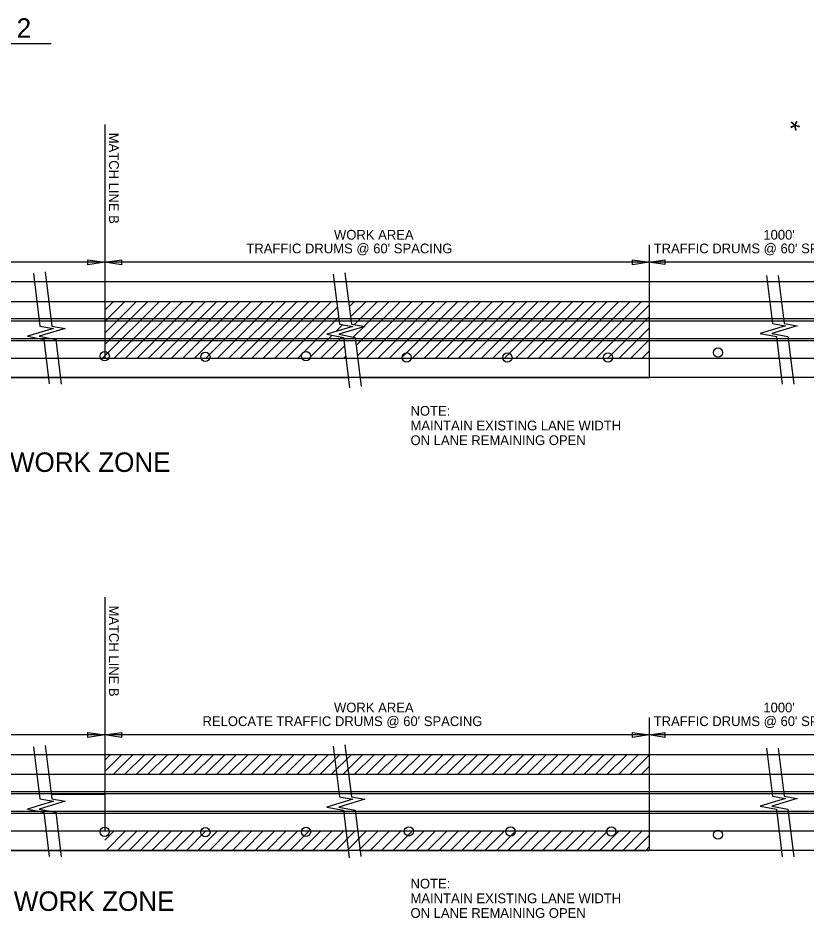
# Model space of a CAD drawing. Extents: x 1930579 to 1937984, y 596452 to 597630.
# Drawn here: x 1936944 to 1937430, y 596642 to 597197 of the extents above; entities that cross this region are included whole.
import ezdxf

# ---------------------------------------------------------------- set-up
doc = ezdxf.new("R2010")
doc.units = 0
doc.layers.add('Default', color=7, linetype='Continuous')
doc.layers.add('R_Border', color=7, linetype='Continuous')

msp = doc.modelspace()

# ---------------------------------------------------------------- linework, layer by layer
at = {"layer": 'Default'}
for p, q in [((1936835.84, 597181.22), (1936964.15, 597181.22)), ((1936997.05, 597131.34), (1936997.05, 596996.89)), ((1937332.4, 597057.24), (1937332.4, 596975.31)), ((1936997.05, 597046.45), (1936688.44, 597046.45)), ((1936986.74, 597044.9), (1936986.74, 597048)), ((1936986.74, 597048), (1936997.05, 597046.45)), ((1936997.05, 597046.45), (1936986.74, 597044.9)), ((1936997.05, 597046.45), (1937007.35, 597048)), ((1936997.05, 597047.93), (1936997.05, 596996.89)), ((1936997.05, 597047.92), (1936997.05, 596996.89)), ((1936997.05, 597047.92), (1936997.05, 596987.31)), ((1937332.4, 597046.45), (1936997.05, 597046.45)), ((1937007.35, 597044.9), (1936997.05, 597046.45)), ((1937007.35, 597048), (1937007.35, 597044.9)), ((1937322.09, 597044.9), (1937322.09, 597047.99)), ((1937322.09, 597047.99), (1937332.4, 597046.45)), ((1937332.4, 597046.45), (1937322.09, 597044.9)), ((1937332.4, 597046.45), (1937342.06, 597047.9)), ((1937342.06, 597045), (1937332.4, 597046.45)), ((1937498.74, 597046.45), (1937332.4, 597046.45)), ((1937342.06, 597047.9), (1937342.06, 597045)), ((1937498.74, 597034.31), (1936493.11, 597034.31)), ((1936493.11, 597022.31), (1937498.74, 597022.31)), ((1936995.74, 596987.31), (1937030.74, 597022.31)), ((1936997.05, 596995.68), (1937023.67, 597022.31)), ((1936997.05, 597002.75), (1937016.6, 597022.31)), ((1936997.05, 597009.83), (1937009.53, 597022.31)), ((1936997.05, 597016.9), (1937002.46, 597022.31)), ((1937002.81, 596987.31), (1937037.81, 597022.31)), ((1937009.89, 596987.31), (1937044.89, 597022.31)), ((1937016.96, 596987.31), (1937051.96, 597022.31)), ((1937024.03, 596987.31), (1937059.03, 597022.31)), ((1937031.1, 596987.31), (1937066.1, 597022.31)), ((1937038.17, 596987.31), (1937073.17, 597022.31)), ((1937045.24, 596987.31), (1937080.24, 597022.31)), ((1937052.31, 596987.31), (1937087.31, 597022.31)), ((1937059.38, 596987.31), (1937094.38, 597022.31)), ((1937066.45, 596987.31), (1937101.45, 597022.31)), ((1937073.53, 596987.31), (1937108.53, 597022.31)), ((1937080.6, 596987.31), (1937115.6, 597022.31)), ((1937087.67, 596987.31), (1937122.67, 597022.31)), ((1937094.74, 596987.31), (1937129.74, 597022.31)), ((1937101.81, 596987.31), (1937136.81, 597022.31)), ((1937147.64, 597018.99), (1937150.95, 597022.31)), ((1937148.42, 597012.71), (1937158.02, 597022.31)), ((1937150.83, 597008.04), (1937165.09, 597022.31)), ((1937152, 596995.07), (1937179.24, 597022.31)), ((1937152.76, 596988.76), (1937186.31, 597022.31)), ((1937156.84, 597006.98), (1937172.17, 597022.31)), ((1937158.38, 596987.31), (1937193.38, 597022.31)), ((1937165.45, 596987.31), (1937200.45, 597022.31)), ((1937172.52, 596987.31), (1937207.52, 597022.31)), ((1937179.59, 596987.31), (1937214.59, 597022.31)), ((1937186.66, 596987.31), (1937221.66, 597022.31)), ((1937193.73, 596987.31), (1937228.73, 597022.31)), ((1937200.8, 596987.31), (1937235.8, 597022.31)), ((1937207.88, 596987.31), (1937242.88, 597022.31)), ((1937214.95, 596987.31), (1937249.95, 597022.31)), ((1937222.02, 596987.31), (1937257.02, 597022.31)), ((1937229.09, 596987.31), (1937264.09, 597022.31)), ((1937236.16, 596987.31), (1937271.16, 597022.31)), ((1937243.23, 596987.31), (1937278.23, 597022.31)), ((1937250.3, 596987.31), (1937285.3, 597022.31)), ((1937257.37, 596987.31), (1937292.37, 597022.31)), ((1937264.44, 596987.31), (1937299.44, 597022.31)), ((1937271.52, 596987.31), (1937306.52, 597022.31)), ((1937278.59, 596987.31), (1937313.59, 597022.31)), ((1937285.66, 596987.31), (1937320.66, 597022.31)), ((1937292.73, 596987.31), (1937327.73, 597022.31)), ((1937108.88, 596987.31), (1937140.38, 597018.81)), ((1937299.8, 596987.31), (1937332.4, 597019.91)), ((1937498.74, 597011.52), (1936493.11, 597011.52)), ((1937498.74, 597010.14), (1936493.11, 597010.14)), ((1937115.95, 596987.31), (1937141.16, 597012.52)), ((1937306.87, 596987.31), (1937332.4, 597012.83)), ((1937139.45, 597003.73), (1937143.72, 597008.01)), ((1937150.22, 597000.37), (1937156.57, 597006.72)), ((1937313.94, 596987.31), (1937332.4, 597005.76)), ((1937498.74, 596999.34), (1936493.11, 596999.34)), ((1937123.02, 596987.31), (1937137.15, 597001.44)), ((1937130.09, 596987.31), (1937143.09, 597000.3)), ((1937321.01, 596987.31), (1937332.4, 596998.69)), ((1937498.74, 596998.03), (1936493.11, 596998.03)), ((1937137.17, 596987.31), (1937144.74, 596994.88)), ((1936493.11, 596987.31), (1937498.74, 596987.31)), ((1937144.24, 596987.31), (1937145.5, 596988.57)), ((1937328.08, 596987.31), (1937332.4, 596991.62)), ((1937498.74, 596975.31), (1936493.11, 596975.31)), ((1936757.75, 596975.31), (1937032.82, 596975.31)), ((1936970.07, 596975.31), (1936996.83, 596975.31)), ((1936996.83, 596975.31), (1937147.44, 596975.31)), ((1937155.09, 596975.31), (1937332.4, 596975.31)), ((1936997.05, 596839.97), (1936997.05, 596705.52)), ((1937332.4, 596765.87), (1937332.4, 596683.94)), ((1936997.05, 596755.08), (1936688.44, 596755.08)), ((1936986.74, 596753.53), (1936986.74, 596756.63)), ((1936986.74, 596756.63), (1936997.05, 596755.08)), ((1936997.05, 596755.08), (1936986.74, 596753.53)), ((1936997.05, 596755.08), (1937007.35, 596756.63)), ((1936997.05, 596756.56), (1936997.05, 596705.52)), ((1936997.05, 596756.55), (1936997.05, 596705.52)), ((1936997.05, 596756.55), (1936997.05, 596695.94)), ((1937332.4, 596755.08), (1936997.05, 596755.08)), ((1937007.35, 596753.53), (1936997.05, 596755.08)), ((1937007.35, 596756.63), (1937007.35, 596753.53)), ((1937322.09, 596753.53), (1937322.09, 596756.62)), ((1937322.09, 596756.62), (1937332.4, 596755.08)), ((1937332.4, 596755.08), (1937322.09, 596753.53)), ((1937332.4, 596755.08), (1937342.06, 596756.53)), ((1937498.74, 596755.08), (1937332.4, 596755.08)), ((1937342.06, 596753.63), (1937332.4, 596755.08)), ((1937342.06, 596756.53), (1937342.06, 596753.63)), ((1937498.74, 596742.94), (1936493.11, 596742.94)), ((1936997.05, 596732.6), (1937007.39, 596742.94)), ((1936997.05, 596739.67), (1937000.32, 596742.94)), ((1937002.46, 596730.94), (1937014.46, 596742.94)), ((1937009.53, 596730.94), (1937021.53, 596742.94)), ((1937016.6, 596730.94), (1937028.6, 596742.94)), ((1937023.67, 596730.94), (1937035.67, 596742.94)), ((1937030.74, 596730.94), (1937042.74, 596742.94)), ((1937037.81, 596730.94), (1937049.81, 596742.94)), ((1937044.89, 596730.94), (1937056.89, 596742.94)), ((1937051.96, 596730.94), (1937063.96, 596742.94)), ((1937059.03, 596730.94), (1937071.03, 596742.94)), ((1937066.1, 596730.94), (1937078.1, 596742.94)), ((1937073.17, 596730.94), (1937085.17, 596742.94)), ((1937080.24, 596730.94), (1937092.24, 596742.94)), ((1937087.31, 596730.94), (1937099.31, 596742.94)), ((1937094.38, 596730.94), (1937106.38, 596742.94)), ((1937101.45, 596730.94), (1937113.45, 596742.94)), ((1937108.53, 596730.94), (1937120.53, 596742.94)), ((1937115.6, 596730.94), (1937127.6, 596742.94)), ((1937122.67, 596730.94), (1937134.67, 596742.94)), ((1937129.74, 596730.94), (1937141.74, 596742.94)), ((1937136.81, 596730.94), (1937148.81, 596742.94)), ((1937143.88, 596730.94), (1937155.88, 596742.94)), ((1937150.95, 596730.94), (1937162.95, 596742.94)), ((1937158.02, 596730.94), (1937170.02, 596742.94)), ((1937165.09, 596730.94), (1937177.09, 596742.94)), ((1937172.17, 596730.94), (1937184.17, 596742.94)), ((1937179.24, 596730.94), (1937191.24, 596742.94)), ((1937186.31, 596730.94), (1937198.31, 596742.94)), ((1937193.38, 596730.94), (1937205.38, 596742.94)), ((1937200.45, 596730.94), (1937212.45, 596742.94)), ((1937207.52, 596730.94), (1937219.52, 596742.94)), ((1937214.59, 596730.94), (1937226.59, 596742.94)), ((1937221.66, 596730.94), (1937233.66, 596742.94)), ((1937228.73, 596730.94), (1937240.73, 596742.94)), ((1937235.8, 596730.94), (1937247.8, 596742.94)), ((1937242.88, 596730.94), (1937254.88, 596742.94)), ((1937249.95, 596730.94), (1937261.95, 596742.94)), ((1937257.02, 596730.94), (1937269.02, 596742.94)), ((1937264.09, 596730.94), (1937276.09, 596742.94)), ((1937271.16, 596730.94), (1937283.16, 596742.94)), ((1937278.23, 596730.94), (1937290.23, 596742.94)), ((1937285.3, 596730.94), (1937297.3, 596742.94)), ((1937292.37, 596730.94), (1937304.37, 596742.94)), ((1937299.44, 596730.94), (1937311.44, 596742.94)), ((1937306.52, 596730.94), (1937318.52, 596742.94)), ((1937313.59, 596730.94), (1937325.59, 596742.94)), ((1937320.66, 596730.94), (1937332.66, 596742.94)), ((1937327.73, 596730.94), (1937332.4, 596735.61)), ((1936493.11, 596730.94), (1937498.74, 596730.94)), ((1937498.74, 596720.15), (1936493.11, 596720.15)), ((1937498.74, 596718.77), (1936493.11, 596718.77)), ((1936964.36, 596718.71), (1936997.05, 596718.71)), ((1937498.74, 596707.98), (1936493.11, 596707.98)), ((1937498.74, 596706.66), (1936493.11, 596706.66)), ((1936493.11, 596695.94), (1937498.74, 596695.94)), ((1936997.05, 596690.17), (1937002.81, 596695.94)), ((1936997.89, 596683.94), (1937009.89, 596695.94)), ((1937004.96, 596683.94), (1937016.96, 596695.94)), ((1937012.03, 596683.94), (1937024.03, 596695.94)), ((1937019.1, 596683.94), (1937031.1, 596695.94)), ((1937026.17, 596683.94), (1937038.17, 596695.94)), ((1937033.24, 596683.94), (1937045.24, 596695.94)), ((1937040.31, 596683.94), (1937052.31, 596695.94)), ((1937047.38, 596683.94), (1937059.38, 596695.94)), ((1937054.45, 596683.94), (1937066.45, 596695.94)), ((1937061.53, 596683.94), (1937073.53, 596695.94)), ((1937068.6, 596683.94), (1937080.6, 596695.94)), ((1937075.67, 596683.94), (1937087.67, 596695.94)), ((1937082.74, 596683.94), (1937094.74, 596695.94)), ((1937089.81, 596683.94), (1937101.81, 596695.94)), ((1937096.88, 596683.94), (1937108.88, 596695.94)), ((1937103.95, 596683.94), (1937115.95, 596695.94)), ((1937111.02, 596683.94), (1937123.02, 596695.94)), ((1937118.09, 596683.94), (1937130.09, 596695.94)), ((1937125.17, 596683.94), (1937137.17, 596695.94)), ((1937132.24, 596683.94), (1937144.24, 596695.94)), ((1937139.31, 596683.94), (1937151.31, 596695.94)), ((1937146.38, 596683.94), (1937158.38, 596695.94)), ((1937153.45, 596683.94), (1937165.45, 596695.94)), ((1937160.52, 596683.94), (1937172.52, 596695.94)), ((1937167.59, 596683.94), (1937179.59, 596695.94)), ((1937174.66, 596683.94), (1937186.66, 596695.94)), ((1937181.73, 596683.94), (1937193.73, 596695.94)), ((1937188.8, 596683.94), (1937200.8, 596695.94)), ((1937195.88, 596683.94), (1937207.88, 596695.94)), ((1937202.95, 596683.94), (1937214.95, 596695.94)), ((1937210.02, 596683.94), (1937222.02, 596695.94)), ((1937217.09, 596683.94), (1937229.09, 596695.94)), ((1937224.16, 596683.94), (1937236.16, 596695.94)), ((1937231.23, 596683.94), (1937243.23, 596695.94)), ((1937238.3, 596683.94), (1937250.3, 596695.94)), ((1937245.37, 596683.94), (1937257.37, 596695.94)), ((1937252.44, 596683.94), (1937264.44, 596695.94)), ((1937259.52, 596683.94), (1937271.52, 596695.94)), ((1937266.59, 596683.94), (1937278.59, 596695.94)), ((1937273.66, 596683.94), (1937285.66, 596695.94)), ((1937280.73, 596683.94), (1937292.73, 596695.94)), ((1937287.8, 596683.94), (1937299.8, 596695.94)), ((1937294.87, 596683.94), (1937306.87, 596695.94)), ((1937301.94, 596683.94), (1937313.94, 596695.94)), ((1937309.01, 596683.94), (1937321.01, 596695.94)), ((1937316.08, 596683.94), (1937328.08, 596695.94)), ((1937323.16, 596683.94), (1937332.4, 596693.18)), ((1937498.74, 596683.94), (1936493.11, 596683.94)), ((1936757.75, 596683.94), (1937032.82, 596683.94)), ((1936970.07, 596683.94), (1936996.83, 596683.94)), ((1936996.83, 596683.94), (1937147.44, 596683.94)), ((1937155.09, 596683.94), (1937332.4, 596683.94)), ((1937330.23, 596683.94), (1937332.4, 596686.11))]:
    msp.add_line(p, q, dxfattribs=at)
for points in [[(1936953.13, 597039.54), (1936957.19, 597007.1), (1936965.44, 597005.64), (1936949.42, 597000.78), (1936959.62, 596998.84), (1936962.9, 596971.51)], [(1936960.31, 597040.43), (1936964.47, 597007.1), (1936972.73, 597005.64), (1936956.7, 597000.78), (1936966.9, 596998.84), (1936970.2, 596971.4)], [(1937137.85, 597039.06), (1937141.68, 597008.37), (1937149.94, 597006.91), (1937133.91, 597002.05), (1937144.11, 597000.11), (1937147.85, 596969.01)], [(1937145.02, 597039.96), (1937148.97, 597008.37), (1937157.22, 597006.91), (1937141.2, 597002.05), (1937151.39, 597000.11), (1937155.03, 596969.87)], [(1937404.64, 597038.31), (1937408.33, 597008.71), (1937416.4, 597007.29), (1937400.75, 597002.54), (1937410.71, 597000.64), (1937414.23, 596971.31)], [(1937411.75, 597038.31), (1937415.45, 597008.71), (1937423.51, 597007.29), (1937407.86, 597002.54), (1937417.82, 597000.64), (1937421.35, 596971.31)], [(1937144.97, 596749), (1937148.97, 596717), (1937157.22, 596715.54), (1937141.2, 596710.68), (1937151.39, 596708.74), (1937154.82, 596680.23)], [(1936953.18, 596747.77), (1936957.19, 596715.73), (1936965.44, 596714.27), (1936949.42, 596709.41), (1936959.62, 596707.47), (1936962.9, 596680.14)], [(1936960.36, 596748.67), (1936964.47, 596715.73), (1936972.73, 596714.27), (1936956.7, 596709.41), (1936966.9, 596707.47), (1936970.2, 596680.03)], [(1937137.8, 596748.1), (1937141.68, 596717), (1937149.94, 596715.54), (1937133.91, 596710.68), (1937144.11, 596708.74), (1937147.64, 596679.37)], [(1937404.64, 596746.94), (1937408.33, 596717.34), (1937416.4, 596715.92), (1937400.75, 596711.17), (1937410.71, 596709.27), (1937414.23, 596679.94)], [(1937411.75, 596746.94), (1937415.45, 596717.34), (1937423.51, 596715.92), (1937407.86, 596711.17), (1937417.82, 596709.27), (1937421.35, 596679.94)]]:
    msp.add_lwpolyline(points, dxfattribs=at)
for centre in [(1937374.75, 596990.76), (1936997.05, 596988.6), (1937059.04, 596988.15), (1937121.03, 596988.57), (1937183.02, 596987.81), (1937245.02, 596987.66), (1937307.01, 596987.81), (1936997.05, 596695.46), (1937059.04, 596695.18), (1937121.03, 596695.41), (1937184.37, 596695.7), (1937247.04, 596695.68), (1937309.04, 596695.68), (1937374.75, 596693.65)]:
    msp.add_circle(centre, 2.87, dxfattribs=at)

# ---------------------------------------------------------------- texts
for s, height, rotation, p in [('STAGES 1   & 2', 12, 360, (1936835.84, 597184.79)), ('MATCH LINE B', 6, 270, (1936999.75, 597126.26)), ('WORK AREA', 6, 360, (1937138.26, 597060.38)), ("1000'", 6, 360, (1937402.67, 597060.38)), ("TRAFFIC DRUMS @ 60' SPACING", 6, 360, (1937084.29, 597051.95)), ("TRAFFIC DRUMS @ 60' SPACING", 6, 360, (1937335.13, 597051.95)), ('DIVERSION FOR LT. LANE WORK ZONE', 12, 360, (1936733.6, 596917.22)), ('MATCH LINE B', 6, 270, (1936999.75, 596834.89)), ('WORK AREA', 6, 360, (1937138.26, 596769.01)), ("1000'", 6, 360, (1937402.67, 596769.01)), ("RELOCATE TRAFFIC DRUMS @ 60' SPACING", 6, 360, (1937057.29, 596760.58)), ("TRAFFIC DRUMS @ 60' SPACING", 6, 360, (1937335.13, 596760.58)), ('DIVERSION FOR RT. LANE WORK ZONE', 12, 360, (1936733.32, 596646.67))]:
    msp.add_text(s, height=height, rotation=rotation, dxfattribs=at).set_placement(p)
at = {"layer": 'R_Border'}
for s, height, rotation, p in [('*', 12, 45, (1937426.11, 597122.28)), ('NOTE:', 6, 360, (1937185.39, 596951.85)), ('MAINTAIN EXISTING LANE WIDTH', 6, 360, (1937185.39, 596942.8)), ('ON LANE REMAINING OPEN', 6, 360, (1937185.39, 596933.75)), ('NOTE:', 6, 360, (1937185.39, 596660.48)), ('MAINTAIN EXISTING LANE WIDTH', 6, 360, (1937185.39, 596651.43)), ('ON LANE REMAINING OPEN', 6, 360, (1937185.39, 596642.38))]:
    msp.add_text(s, height=height, rotation=rotation, dxfattribs=at).set_placement(p)

doc.saveas('drawing.dxf')
